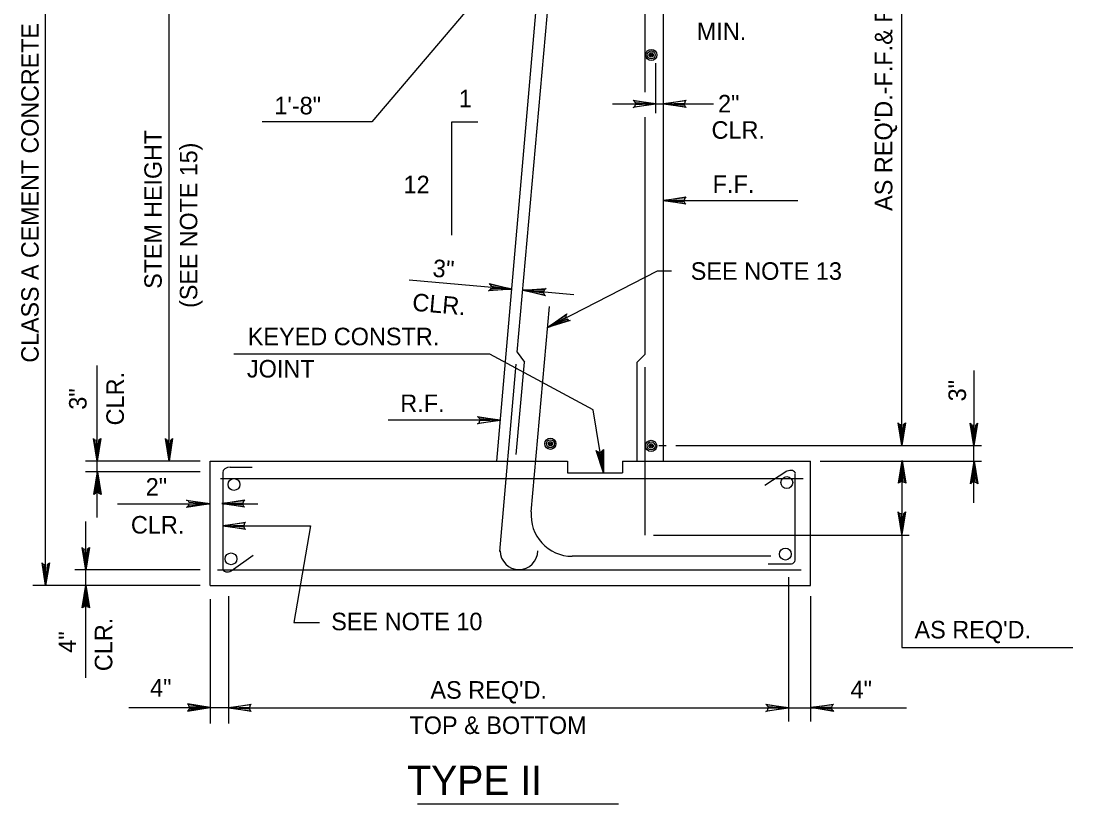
# Model space of a CAD drawing. Extents: x 235 to 2276, y 116 to 1308.
# Drawn here: x 817 to 996.9, y 415.9 to 549.7 of the extents above; entities that cross this region are included whole.
import ezdxf

# ---------------------------------------------------------------- set-up
doc = ezdxf.new("R2010")
doc.units = 0
doc.layers.add('1', color=7, linetype='Continuous')

msp = doc.modelspace()

# ---------------------------------------------------------------- linework, layer by layer
at = {"layer": '1'}
for p, q in [((821.17, 453.24), (821.17, 592.46)), ((926.83, 474.49), (926.83, 591.53)), ((967.61, 477.15), (967.61, 588.71)), ((842.27, 474.49), (842.27, 583.87)), ((923.71, 537.57), (923.71, 578.09)), ((901.8, 493.09), (909.14, 575.59)), ((898.36, 474.49), (906.33, 566.37)), ((892.89, 551.21), (876.95, 532.46)), ((925.51, 533.96), (925.51, 542.5)), ((918.09, 535.54), (925.51, 535.54)), ((925.51, 535.54), (926.83, 535.54)), ((926.83, 535.54), (935.38, 535.54)), ((923.71, 492.74), (923.71, 533.28)), ((876.95, 532.46), (858.17, 532.46)), ((890.66, 532.46), (895.07, 532.46)), ((890.66, 513.09), (890.66, 532.46)), ((926.83, 519.03), (949.8, 519.03)), ((925.78, 506.94), (907.02, 497.31)), ((928.21, 506.94), (925.78, 506.94)), ((900.7, 503.87), (883.35, 505.4)), ((911.49, 502.93), (902.74, 503.71)), ((904.22, 465.83), (907.34, 500.9)), ((901.8, 493.09), (903.05, 491.37)), ((897.15, 492.78), (853.36, 492.78)), ((914.8, 483.24), (897.15, 492.78)), ((901.64, 475.59), (903.05, 491.37)), ((922.34, 491.37), (923.71, 492.74)), ((922.34, 474.49), (922.34, 491.37)), ((829.98, 474.49), (829.98, 490.82)), ((898.83, 459.03), (901.64, 491.06)), ((923.71, 461.84), (923.71, 490.51)), ((979.96, 477.15), (979.96, 489.97)), ((916.56, 472.46), (914.8, 483.24)), ((879.76, 481.53), (898.99, 481.53)), ((926.05, 477.15), (927.3, 477.15)), ((928.97, 477.15), (981.21, 477.15)), ((979.94, 467.34), (979.94, 477.15)), ((847.59, 474.49), (828, 474.49)), ((829.98, 464.81), (829.98, 474.49)), ((849.3, 453.24), (849.3, 474.49)), ((849.3, 474.49), (910.43, 474.49)), ((856.49, 473.4), (852.74, 473.4)), ((910.43, 474.49), (910.43, 472.46)), ((919.8, 474.49), (951.99, 474.49)), ((919.8, 474.49), (919.8, 472.46)), ((951.99, 453.24), (951.99, 474.49)), ((953.62, 474.49), (981.21, 474.49)), ((967.61, 474.49), (967.61, 461.84)), ((847.59, 472.62), (828, 472.62)), ((851.06, 471.51), (950.74, 471.51)), ((851.49, 472.46), (851.49, 456.06)), ((910.43, 472.46), (919.8, 472.46)), ((947.93, 472.78), (944.18, 470.28)), ((949.33, 457.56), (949.33, 472.31)), ((833.46, 467.2), (849.3, 467.2)), ((851.49, 467.2), (857.48, 467.2)), ((828.05, 453.24), (828.05, 464.18)), ((851.48, 463.42), (866.45, 463.42)), ((866.45, 463.42), (863.61, 446.89)), ((925.11, 461.84), (960.74, 461.84)), ((960.74, 461.84), (968.86, 461.84)), ((967.61, 461.84), (967.61, 442.62)), ((852.89, 455.74), (856.64, 458.4)), ((945.17, 458.21), (911.19, 458.21)), ((847.59, 455.9), (826.17, 455.9)), ((850.57, 455.9), (950.36, 455.9)), ((944.75, 456.93), (948.71, 456.93)), ((948.24, 454.65), (948.24, 429.96)), ((847.59, 453.24), (818.99, 453.24)), ((828.05, 437.45), (828.05, 453.24)), ((849.3, 453.24), (951.99, 453.24)), ((849.3, 450.9), (849.3, 429.65)), ((852.46, 451.37), (852.46, 429.65)), ((951.99, 451.37), (951.99, 429.96)), ((863.61, 446.89), (867.98, 446.89)), ((967.61, 442.62), (996.87, 442.62)), ((852.46, 432.31), (835.38, 432.31)), ((852.46, 432.31), (948.24, 432.31)), ((948.24, 432.31), (968.4, 432.31)), ((884.78, 415.87), (919.15, 415.87))]:
    msp.add_line(p, q, dxfattribs=at)
for points in [[(921.76, 536.04), (922.01, 535.79), (925.51, 535.54), (921.76, 536.04), (921.63, 536.16), (925.51, 535.54), (922.01, 535.41), (921.88, 535.04), (925.51, 535.54), (921.63, 534.91), (921.88, 535.04)], [(930.58, 535.04), (930.46, 535.29), (926.83, 535.54), (930.58, 535.04), (930.71, 534.91), (926.83, 535.54), (930.46, 535.66), (930.58, 536.04), (926.83, 535.54), (930.71, 536.16), (930.58, 536.04)], [(930.55, 518.51), (930.43, 518.76), (926.8, 519.01), (930.55, 518.51), (930.68, 518.38), (926.8, 519.01), (930.43, 519.13), (930.55, 519.51), (926.8, 519.01), (930.68, 519.63), (930.55, 519.51)], [(897.22, 504.67), (897.34, 504.39), (900.95, 503.87), (897.22, 504.67), (897.05, 504.86), (900.95, 503.87), (897.31, 504.01), (897.15, 503.75), (900.95, 503.87), (896.93, 503.59), (897.15, 503.75)], [(906.49, 502.91), (906.37, 503.19), (902.77, 503.72), (906.49, 502.91), (906.67, 502.73), (902.77, 503.72), (906.4, 503.57), (906.56, 503.83), (902.77, 503.72), (906.78, 503.99), (906.56, 503.83)], [(910.61, 498.59), (910.36, 498.77), (907.02, 497.31), (910.61, 498.59), (910.86, 498.53), (907.02, 497.31), (910.18, 499.11), (910.18, 499.41), (907.02, 497.31), (910.28, 499.66), (910.18, 499.41)], [(895.13, 481.99), (895.38, 481.74), (898.88, 481.49), (895.13, 481.99), (895, 482.12), (898.88, 481.49), (895.38, 481.37), (895.25, 480.99), (898.88, 481.49), (895, 480.87), (895.25, 480.99)], [(968.08, 480.91), (967.83, 480.66), (967.58, 477.16), (968.08, 480.91), (968.2, 481.04), (967.58, 477.16), (967.45, 480.66), (967.08, 480.79), (967.58, 477.16), (966.95, 481.04), (967.08, 480.79)], [(980.44, 480.83), (980.19, 480.58), (979.94, 477.08), (980.44, 480.83), (980.56, 480.95), (979.94, 477.08), (979.81, 480.58), (979.44, 480.7), (979.94, 477.08), (979.31, 480.95), (979.44, 480.7)], [(830.48, 478.24), (830.23, 477.99), (829.98, 474.49), (830.48, 478.24), (830.61, 478.37), (829.98, 474.49), (829.86, 477.99), (829.48, 478.12), (829.98, 474.49), (829.36, 478.37), (829.48, 478.12)], [(842.77, 478.24), (842.52, 477.99), (842.27, 474.49), (842.77, 478.24), (842.89, 478.37), (842.27, 474.49), (842.14, 477.99), (841.77, 478.12), (842.27, 474.49), (841.64, 478.37), (841.77, 478.12)], [(916.42, 476.27), (916.17, 476.09), (916.56, 472.46), (916.42, 476.27), (916.55, 476.49), (916.56, 472.46), (915.8, 476.02), (915.51, 476.11), (916.56, 472.46), (915.3, 476.28), (915.51, 476.11)], [(967.16, 470.81), (967.41, 470.94), (967.66, 474.56), (967.16, 470.81), (967.04, 470.69), (967.66, 474.56), (967.79, 470.94), (968.16, 470.81), (967.66, 474.56), (968.29, 470.69), (968.16, 470.81)], [(979.46, 470.74), (979.71, 470.87), (979.96, 474.49), (979.46, 470.74), (979.33, 470.62), (979.96, 474.49), (980.08, 470.87), (980.46, 470.74), (979.96, 474.49), (980.58, 470.62), (980.46, 470.74)], [(829.51, 468.91), (829.76, 469.04), (830.01, 472.66), (829.51, 468.91), (829.39, 468.79), (830.01, 472.66), (830.14, 469.04), (830.51, 468.91), (830.01, 472.66), (830.64, 468.79), (830.51, 468.91)], [(845.53, 467.69), (845.65, 467.44), (849.28, 467.19), (845.53, 467.69), (845.28, 467.82), (849.28, 467.19), (845.65, 467.07), (845.53, 466.82), (849.28, 467.19), (845.28, 466.57), (845.53, 466.82)], [(855.07, 466.71), (854.95, 466.96), (851.32, 467.21), (855.07, 466.71), (855.2, 466.59), (851.32, 467.21), (854.95, 467.34), (855.07, 467.71), (851.32, 467.21), (855.2, 467.84), (855.07, 467.71)], [(968.11, 465.71), (967.86, 465.46), (967.61, 461.96), (968.11, 465.71), (968.23, 465.83), (967.61, 461.96), (967.48, 465.46), (967.11, 465.58), (967.61, 461.96), (966.98, 465.83), (967.11, 465.58)], [(855.23, 462.92), (855.1, 463.17), (851.48, 463.42), (855.23, 462.92), (855.35, 462.8), (851.48, 463.42), (855.1, 463.55), (855.23, 463.92), (851.48, 463.42), (855.35, 464.05), (855.23, 463.92)], [(828.54, 459.6), (828.29, 459.35), (828.04, 455.85), (828.54, 459.6), (828.66, 459.73), (828.04, 455.85), (827.91, 459.35), (827.54, 459.48), (828.04, 455.85), (827.41, 459.73), (827.54, 459.48)], [(821.67, 456.97), (821.42, 456.72), (821.17, 453.22), (821.67, 456.97), (821.8, 457.09), (821.17, 453.22), (821.05, 456.72), (820.67, 456.84), (821.17, 453.22), (820.55, 457.09), (820.67, 456.84)], [(827.56, 449.52), (827.81, 449.64), (828.06, 453.27), (827.56, 449.52), (827.44, 449.39), (828.06, 453.27), (828.19, 449.64), (828.56, 449.52), (828.06, 453.27), (828.69, 449.39), (828.56, 449.52)], [(845.58, 431.86), (845.7, 432.11), (849.33, 432.36), (845.58, 431.86), (845.45, 431.74), (849.33, 432.36), (845.7, 432.49), (845.58, 432.86), (849.33, 432.36), (845.45, 432.99), (845.58, 432.86)], [(856.21, 431.81), (856.08, 432.06), (852.46, 432.31), (856.21, 431.81), (856.33, 431.68), (852.46, 432.31), (856.08, 432.43), (856.21, 432.81), (852.46, 432.31), (856.33, 432.93), (856.21, 432.81)], [(944.44, 432.79), (944.69, 432.54), (948.19, 432.29), (944.44, 432.79), (944.31, 432.92), (948.19, 432.29), (944.69, 432.17), (944.56, 431.79), (948.19, 432.29), (944.31, 431.67), (944.56, 431.79)], [(955.77, 431.83), (955.64, 432.08), (952.02, 432.33), (955.77, 431.83), (955.89, 431.7), (952.02, 432.33), (955.64, 432.45), (955.77, 432.83), (952.02, 432.33), (955.89, 432.95), (955.77, 432.83)]]:
    msp.add_lwpolyline(points, dxfattribs=at)
for centre, radius in [((924.74, 543.91), 0.954), ((924.74, 543.91), 0.681), ((924.74, 543.91), 0.372), ((924.74, 543.91), 0.188), ((924.74, 543.91), 0.0805), ((907.49, 477.44), 0.954), ((907.49, 477.44), 0.681), ((907.49, 477.44), 0.372), ((907.49, 477.44), 0.188), ((907.49, 477.44), 0.0805), ((924.72, 477.08), 0.954), ((924.72, 477.08), 0.681), ((924.72, 477.08), 0.372), ((924.72, 477.08), 0.188), ((924.72, 477.08), 0.0805), ((853.37, 470.48), 1.01), ((947.92, 470.81), 1.01), ((852.87, 457.77), 1.01), ((947.68, 458.58), 1.01)]:
    msp.add_circle(centre, radius, dxfattribs=at)
for centre, radius, start, end in [((911.19, 465.21), 7, 174.9079, 270), ((902.12, 459.15), 3.22, 180, 0), ((948.71, 457.56), 0.625, 270, 0)]:
    msp.add_arc(centre, radius, start, end, dxfattribs=at)
for centre, major_axis, ratio, start_param, end_param in [((852.75, 472.54), (-1.3, 0), 0.697544, 4.712389, 6.283185), ((948.58, 472.38), (-0.812, 0), 0.632693, 3.141593, 5.497787), ((852.27, 456.1), (0.812, 0), 0.697544, 3.141593, 5.497787)]:
    msp.add_ellipse(centre, major_axis=major_axis, ratio=ratio, start_param=start_param, end_param=end_param, dxfattribs=at)

# ---------------------------------------------------------------- texts
for s, height, rotation, p in [("AS REQ'D.-F.F.& R.F.", 3, 90, (965.98, 517.24)), ('CLASS A CEMENT CONCRETE', 2.97, 90, (819.97, 491.31)), ('STEM HEIGHT', 2.97, 90, (841.02, 503.94)), ('(SEE NOTE 15)', 2.97, 90, (847.1, 500.67)), ('3"', 3, 354.9865, (887.26, 506.01)), ('CLR.', 3, 354.9865, (883.78, 500.2)), ('CLR.', 3, 90, (834.55, 480.58)), ('3"', 3, 90, (978.57, 484.69)), ('3"', 3, 90, (828.17, 483.26)), ('CLR.', 3, 90, (832.57, 438.57)), ('4"', 3, 90, (826.38, 441.72))]:
    msp.add_text(s, height=height, rotation=rotation, dxfattribs=at).set_placement(p)
for s, height, p in [('MIN.', 3, (932.53, 546.45)), ('1 ', 3, (891.82, 534.95)), ('1\'-8"', 3.003, (860.27, 533.75)), (' 2"', 3, (935.05, 534.08)), ('CLR.', 3, (935.05, 529.58)), ('12', 3.003, (882.38, 520.26)), ('F.F.', 3, (935.24, 520.33)), ('SEE NOTE 13', 3, (931.49, 505.47)), ('KEYED CONSTR.', 3, (855.73, 494.28)), ('JOINT', 3, (855.59, 488.77)), ('R.F.', 3, (881.82, 482.86)), ('2"', 3.003, (838.28, 468.57)), ('CLR.', 3, (835.75, 462.09)), ('SEE NOTE 10', 3, (870.01, 445.56)), ("AS REQ'D.", 3, (969.76, 444.16)), ('4"', 3.003, (839.03, 434.22)), ("AS REQ'D.", 3, (886.97, 433.86)), ('4"', 3.003, (958.83, 433.93)), ('TOP & BOTTOM', 3, (883.38, 427.83)), (' TYPE II', 5, (881.16, 417.4))]:
    msp.add_text(s, height=height, dxfattribs=at).set_placement(p)

doc.saveas('drawing.dxf')
